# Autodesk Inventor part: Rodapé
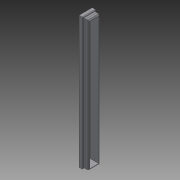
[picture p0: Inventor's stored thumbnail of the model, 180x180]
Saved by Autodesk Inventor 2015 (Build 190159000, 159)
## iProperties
Created: 2015-04
Part Number: Rodapé
Material: Generic
Document SubType Name: Modeling
Designer: suporte
Density: 1 g/cm^3
Appearance: Default
Author: suporte
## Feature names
1. Sweep1
## Parameters: d4 = 7 mm, d6 = 7 mm, d9 = 45 mm, d10 = 5 mm, d12 = 5 mm, d13 = 11 mm, d14 = 125 mm, d16 = 0, d17 = 0
